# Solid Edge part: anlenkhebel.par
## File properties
Author: administrator
Template: Normal.par
Last saved by: administrator
Revision: 1
Application: Solid Edge
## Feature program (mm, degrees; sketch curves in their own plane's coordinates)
sketch for "unnamed Protrusion 1" plane through (0, 0, 0) normal (0, -1, 0) x-axis (1, 0, 0)
extrude "unnamed Protrusion 1" add finite 5 symmetric
sketch for "unnamed Cutout 1" #1 plane through (0, -2.5, 0) normal (0, -1, 0) x-axis (1, 0, 0)
  circle centre (0, -10) radius 2.5
sketch for "unnamed Cutout 1" #2 plane through (0, -2.5, 0) normal (0, -1, 0) x-axis (1, 0, 0)
extrude "unnamed Cutout 1" cut finite 82.55 along -normal
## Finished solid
Body 1: solid body, 11 faces, 26 edges, 16 vertices.
  Faces by surface: plane 10, cylinder 1
  Edges by curve: line 24, circle 2
Bounding box of the edges (mm): 10.000 x 5.000 x 30.000, from (-5, -2.5, -15) to (5, 2.5, 15).
Cylindrical faces by radius (mm): R2.5 x1
Planar faces by outward normal: +x 2, +y 1, +z 2, -x 2, -y 1, -z 2
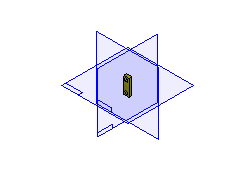
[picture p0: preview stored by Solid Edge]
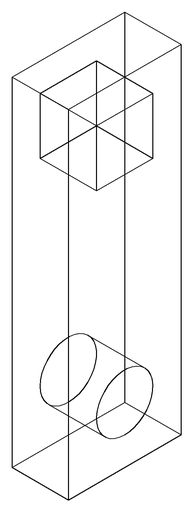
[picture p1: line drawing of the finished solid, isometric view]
